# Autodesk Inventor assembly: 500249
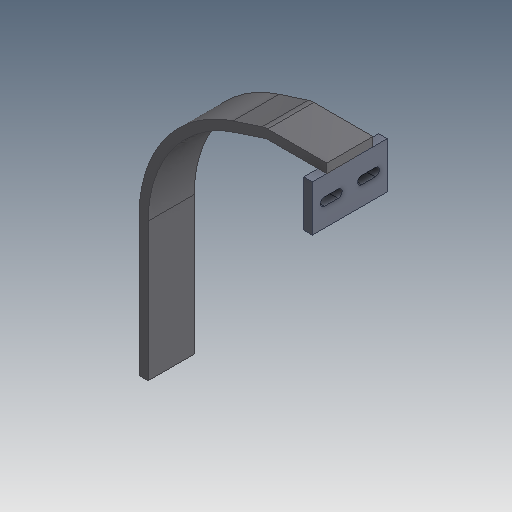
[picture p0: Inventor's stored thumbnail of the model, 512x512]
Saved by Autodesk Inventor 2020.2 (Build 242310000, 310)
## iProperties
Created: 1999-12
Part Number: 500249
Description: WMT-CP,FS,XX,PLOW,MAJOR_FLAP
Document SubType Name: Assembly
Designer: sspink
Mass: 512.782 g
Surface Area: 654.993 cm^2
Volume: 258.578 cm^3
Density: 1.98308 g/cm^3
Control State: 0
Checked Out: False
Last Check In By: gpurviance
Last Check In Date: 2000-01-06
Master: False
Shininess: 0.0
Length Units: 11272
Angle Units: 11279
Time Units: 11290
Mass Units: 11286
Length Display Precision: 3
Angle Display Precision: 2
Compacted: True
Dimensions: 12,1x3,3x8,1 in
Mass: 1,13 lb
DocNumber: 500249.iam
Folder: 01 - Themengebiete\Simplification\01 - Packaging machine\
VDS_Category: 3D Komponenten
Density: 0.0
Volumn: 0.0
Area: 0.0
PropertySet Name: Model Information
Author: sspink
Revision Number: -
Title: arch
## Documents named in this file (3)
- D:\07 - DEMODATEN\OTX 2019 - Dataset - UPDATE - Dez2019\Designs\07-Packing machine\500249.iam
- D:\07 - DEMODATEN\OTX 2019 - Dataset - UPDATE - Dez2019\Designs\07-Packing machine\Parts\ADSK-011317.ipt
- D:\07 - DEMODATEN\OTX 2019 - Dataset - UPDATE - Dez2019\Designs\07-Packing machine\Parts\ADSK-011318.ipt
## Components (2 placed, 2 different names)
1. ADSK-011317:1 — Mate:1, Flush:1, Flush:2
2. ADSK-011318:1 — Mate:1, Flush:1, Flush:2, Flush:3, Flush:4, Mate:2
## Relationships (6: Flush 4, Mate 2)
- Mate:1: ADSK-011317:1 ↔ ADSK-011318:1
- Flush:1: ADSK-011317:1 ↔ ADSK-011318:1
- Flush:2: ADSK-011317:1 ↔ ADSK-011318:1
- Flush:3: ADSK-011318:1
- Flush:4: ADSK-011318:1
- Mate:2: ADSK-011318:1
